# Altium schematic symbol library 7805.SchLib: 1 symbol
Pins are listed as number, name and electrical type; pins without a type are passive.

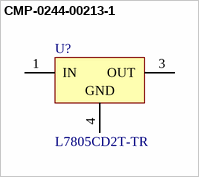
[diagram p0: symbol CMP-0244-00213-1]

## CMP-0244-00213-1
designator U?, comment L7805CD2T-TR
Positive Voltage Regulator, 3-Pin D2PAK, Tape and Reel
footprint TO-263_N (D2-PAK, 4-Leads, Body 9.2x10.2mm, Pitch 2.54mm, Lead Span 15.4mm, IPC Medium Density)
footprint TO-263_M (D2-PAK, 4-Leads, Body 9.2x10.2mm, Pitch 2.54mm, Lead Span 15.4mm, IPC Low Density)
footprint TO-263_L (D2-PAK, 4-Leads, Body 9.2x10.2mm, Pitch 2.54mm, Lead Span 15.4mm, IPC High Density)
pins: 1 IN (power), 3 OUT (power), 4 GND (power)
